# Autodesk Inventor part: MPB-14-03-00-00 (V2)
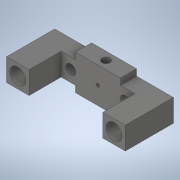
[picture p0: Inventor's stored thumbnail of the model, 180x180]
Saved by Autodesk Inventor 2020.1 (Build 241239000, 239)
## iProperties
Created: 2020-04
Part Number: MPB-14-03-00-00 (V2)
Material: Al 6061
Document SubType Name: Modeling
Designer: Safarabadi
Density: 2.7 g/cm^3
Appearance: Aluminum - Flat
Author: Safarabadi
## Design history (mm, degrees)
derived "MPB-14-03-00-00.ipt"
workplane "Work Plane1"
feature "Solid1::MPB-14-03-00-00.ipt" dims "d0" = 10
tag "TaggingFeature1"
body "Solid1"
other parameters: "d1" = -5
